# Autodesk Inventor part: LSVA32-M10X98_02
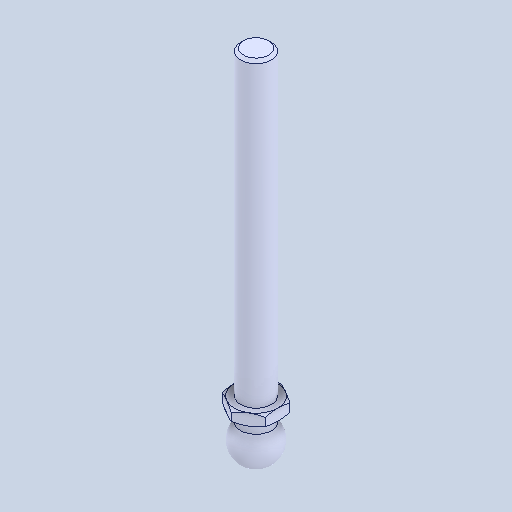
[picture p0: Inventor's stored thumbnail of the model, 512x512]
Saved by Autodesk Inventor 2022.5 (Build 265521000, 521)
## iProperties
Created: 2024-08
Part Number: LSVA32-M10X98_02
Material: 一般
Document SubType Name: Modeling
Designer: ImaoCorp
Density: 1 g/cm^3
Appearance: 既定
Author: ImaoCorp
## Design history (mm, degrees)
feature "LSVA32-M10X98_02"
node "ソリッド1"
